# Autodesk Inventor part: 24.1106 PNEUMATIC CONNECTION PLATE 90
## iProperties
Created: 2007-01
Part Number: 24.1106 PNEUMATIC CONNECTION PLATE 90
Document SubType Name: Modeling
Designer: Andy Moles
Material: Aluminum-6061
Mass: 308.206 g
Surface Area: 230.196 cm^2
Volume: 113.729 cm^3
Density: 2.71 g/cm^3
Author: Andy Moles
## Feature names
1. Extrusion1
2. Hole1
3. Hole2
4. Fillet1
5. Hole3
6. Hole4
7. Extrusion2
8. Chamfer1
